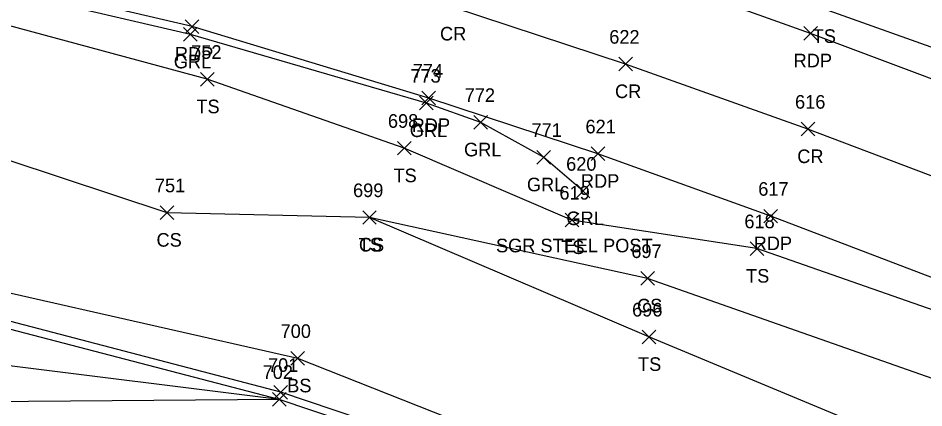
# Model space of a CAD drawing. Extents: x 1599569 to 1610055, y 642560 to 647860.
# Drawn here: x 1602648.3 to 1602781.6, y 647435 to 647492.4 of the extents above; entities that cross this region are included whole.
import ezdxf

# ---------------------------------------------------------------- set-up
doc = ezdxf.new("R2010")
doc.units = 0
for name, color, linetype in [('L_A', 7, 'Continuous'), ('L_I', 7, 'Continuous'), ('L_TIC', 7, 'Continuous'), ('LELB', 7, 'Continuous'), ('P_A', 7, 'Continuous'), ('P_I', 7, 'Continuous'), ('P_TIC', 7, 'Continuous'), ('PET', 7, 'Continuous'), ('PRC', 7, 'Continuous'), ('R_A', 7, 'Continuous'), ('R_C', 7, 'Continuous'), ('R_I', 7, 'Continuous'), ('R_TIC', 7, 'Continuous'), ('RGR', 7, 'Continuous')]:
    doc.layers.add(name, color=color, linetype=linetype)

msp = doc.modelspace()

# ---------------------------------------------------------------- linework, layer by layer
at = {"layer": 'L_TIC'}
for points in [[(1602675.17, 647482.37), (1602677.17, 647484.37)], [(1602677.17, 647482.37), (1602675.17, 647484.37)], [(1602704.16, 647472.23), (1602706.16, 647474.23)], [(1602706.16, 647472.23), (1602704.16, 647474.23)], [(1602669.27, 647462.75), (1602671.27, 647464.75)], [(1602671.27, 647462.75), (1602669.27, 647464.75)], [(1602699.04, 647462.04), (1602701.04, 647464.04)], [(1602701.04, 647462.04), (1602699.04, 647464.04)], [(1602699.04, 647462.04), (1602701.04, 647464.04)], [(1602701.04, 647462.04), (1602699.04, 647464.04)], [(1602728.83, 647461.67), (1602730.83, 647463.67)], [(1602730.83, 647461.67), (1602728.83, 647463.67)], [(1602756.03, 647457.46), (1602758.03, 647459.46)], [(1602758.03, 647457.46), (1602756.03, 647459.46)], [(1602739.96, 647453.08), (1602741.96, 647455.08)], [(1602741.96, 647453.08), (1602739.96, 647455.08)], [(1602740.14, 647444.48), (1602742.14, 647446.48)], [(1602742.14, 647444.48), (1602740.14, 647446.48)], [(1602688.48, 647441.33), (1602690.48, 647443.33)], [(1602690.48, 647441.33), (1602688.48, 647443.33)], [(1602685.76, 647435.3), (1602687.76, 647437.3)], [(1602687.76, 647435.3), (1602685.76, 647437.3)], [(1602685.76, 647435.3), (1602687.76, 647437.3)], [(1602687.76, 647435.3), (1602685.76, 647437.3)], [(1602685.76, 647435.3), (1602687.76, 647437.3)], [(1602687.76, 647435.3), (1602685.76, 647437.3)], [(1602685.99, 647436.34), (1602687.99, 647438.34)], [(1602687.99, 647436.34), (1602685.99, 647438.34)]]:
    msp.add_lwpolyline(points, dxfattribs=at)
at = {"layer": 'LELB'}
for points in [[(1602834.18, 647471.37), (1602800.58, 647481.71), (1602766.83, 647493.71), (1602735.94, 647503.84), (1602713.49, 647512.26), (1602692.59, 647522.64), (1602679.82, 647526.83)], [(1602920.15, 647395.93), (1602878.36, 647413), (1602839.66, 647426.29), (1602797.14, 647444.47), (1602757.03, 647458.46), (1602729.83, 647462.67), (1602705.16, 647473.23), (1602676.17, 647483.37), (1602645.06, 647491.74), (1602608.39, 647499.39), (1602581.9, 647503.71), (1602538.18, 647509.07), (1602515.71, 647510.39), (1602496.95, 647511.81), (1602468.81, 647510.52), (1602437.53, 647504.14), (1602407.66, 647504.45), (1602378.45, 647504.43), (1602350.14, 647499.82), (1602309.52, 647489.18), (1602272.83, 647479.89), (1602236.83, 647468.86)], [(1602844.82, 647413.51), (1602810.8, 647429.9), (1602787.42, 647437.73), (1602740.96, 647454.08), (1602700.04, 647463.04), (1602670.27, 647463.75), (1602639.01, 647474.07), (1602621.95, 647482.89), (1602620.57, 647490.49), (1602611.15, 647487.69), (1602600.84, 647483.48), (1602570.08, 647479.67), (1602551.04, 647482.68)], [(1603012.49, 647326.24), (1602990.45, 647341.3), (1602973.77, 647353.11), (1602953.95, 647363.4), (1602916.83, 647376.34), (1602879.52, 647385.68), (1602861.45, 647391.05), (1602857.96, 647395.91), (1602856.57, 647396.23), (1602848.89, 647379.86), (1602843.21, 647377.7), (1602818.67, 647385.57), (1602771.25, 647404.63), (1602731.78, 647425.59), (1602689.48, 647442.33), (1602646.26, 647452.13), (1602605.47, 647460.82), (1602615.77, 647472.63), (1602617.29, 647479.52), (1602614.47, 647480.43), (1602602, 647462.58), (1602569.34, 647464.61)], [(1602941.78, 647364.94), (1602916.7, 647374.33), (1602878.74, 647383.8), (1602864.18, 647385.07), (1602847.83, 647371.45), (1602840.84, 647371.94), (1602817.04, 647381.69), (1602769.81, 647402.39), (1602730.45, 647422.72), (1602686.99, 647437.34), (1602646.16, 647448.05), (1602607.13, 647455.67), (1602560.59, 647462.73), (1602528.15, 647452.11), (1602504.4, 647431.52), (1602495.06, 647409.31), (1602489.51, 647381.97), (1602486.55, 647364.53)], [(1602997.22, 647343.55), (1602982.64, 647359.24), (1602956.26, 647371.23), (1602923.49, 647383.78), (1602881.48, 647394.49), (1602864.86, 647399.2), (1602857.7, 647404.45), (1602852.15, 647401.21), (1602844.53, 647381.78), (1602821.22, 647392.08), (1602783.51, 647427.85), (1602741.14, 647445.48), (1602700.04, 647463.04)], [(1602941.34, 647363.29), (1602915.67, 647371.75), (1602877.66, 647379.52), (1602865.48, 647379.11), (1602848.78, 647367.3), (1602839.38, 647367.46), (1602815.63, 647378.56), (1602768.2, 647398.54), (1602730, 647421.7), (1602686.76, 647436.3), (1602645.94, 647446.93), (1602606.96, 647454.27), (1602560.51, 647460.83), (1602529.36, 647450.31), (1602505.68, 647431.34)], [(1602686.76, 647436.3), (1602644.67, 647441.5), (1602603.76, 647449.22), (1602559.9, 647457.97), (1602529.4, 647445.04)], [(1602686.76, 647436.3), (1602643.7, 647435.94), (1602601.62, 647443.37), (1602558.17, 647448.12), (1602529.4, 647445.04)]]:
    msp.add_lwpolyline(points, dxfattribs=at)
at = {"layer": 'P_TIC'}
for points in [[(1602672.93, 647490.11), (1602674.93, 647492.11)], [(1602674.93, 647490.11), (1602672.93, 647492.11)], [(1602763.94, 647489.12), (1602765.94, 647491.12)], [(1602765.94, 647489.12), (1602763.94, 647491.12)], [(1602736.72, 647484.6), (1602738.72, 647486.6)], [(1602738.72, 647484.6), (1602736.72, 647486.6)], [(1602707.76, 647479.61), (1602709.76, 647481.61)], [(1602709.76, 647479.61), (1602707.76, 647481.61)], [(1602763.54, 647475.04), (1602765.54, 647477.04)], [(1602765.54, 647475.04), (1602763.54, 647477.04)], [(1602732.65, 647471.41), (1602734.65, 647473.41)], [(1602734.65, 647471.41), (1602732.65, 647473.41)], [(1602758.07, 647462.24), (1602760.07, 647464.24)], [(1602760.07, 647462.24), (1602758.07, 647464.24)]]:
    msp.add_lwpolyline(points, dxfattribs=at)
at = {"layer": 'PET'}
for points in [[(1602905.04, 647435.16), (1602871.23, 647448.73), (1602854.79, 647455.39), (1602851.89, 647458.31), (1602832.84, 647465.97), (1602826.47, 647466.63), (1602798.9, 647477.36), (1602764.94, 647490.12), (1602734.4, 647501.05), (1602712.01, 647507.82), (1602692.31, 647514.03), (1602689.68, 647516.42), (1602659.67, 647523.94), (1602639.42, 647528.36)], [(1602921.43, 647398.55), (1602879.84, 647415.39), (1602841.76, 647430.73), (1602798.53, 647448.18), (1602759.07, 647463.24), (1602733.65, 647472.41), (1602708.76, 647480.61), (1602673.93, 647491.11), (1602636.13, 647499.95), (1602599.54, 647506.52), (1602572.66, 647510.09), (1602538.1, 647513.57), (1602515.34, 647514.89), (1602496.48, 647515.72), (1602467.73, 647515.18), (1602434.16, 647513.35), (1602407.64, 647511.45), (1602378.14, 647507.95), (1602349.73, 647503.67), (1602307.56, 647494.3), (1602272.4, 647484.22), (1602235.37, 647472.94)]]:
    msp.add_lwpolyline(points, dxfattribs=at)
at = {"layer": 'PRC'}
msp.add_lwpolyline([(1602927.12, 647412.15), (1602885.11, 647429.06), (1602847.57, 647444.53), (1602804.05, 647461.06), (1602764.54, 647476.04), (1602737.72, 647485.6), (1602711.98, 647494.07), (1602678.09, 647504.18), (1602638.82, 647513.36), (1602602.08, 647520.13), (1602573.57, 647523.94), (1602538.53, 647527.38), (1602522.02, 647528.41), (1602495.43, 647529.4), (1602476.58, 647529.51), (1602450.94, 647528.8), (1602428.92, 647527.79), (1602401.34, 647525.43), (1602374.1, 647521.93), (1602345.43, 647516.91), (1602315.11, 647510.44), (1602285.69, 647502.77), (1602253.57, 647492.91)], dxfattribs=at)
at = {"layer": 'R_TIC'}
for points in [[(1602672.7, 647488.97), (1602674.7, 647490.97)], [(1602674.7, 647488.97), (1602672.7, 647490.97)], [(1602707.42, 647478.87), (1602709.42, 647480.87)], [(1602709.42, 647478.87), (1602707.42, 647480.87)], [(1602715.41, 647476.03), (1602717.41, 647478.03)], [(1602717.41, 647476.03), (1602715.41, 647478.03)], [(1602724.66, 647470.89), (1602726.66, 647472.89)], [(1602726.66, 647470.89), (1602724.66, 647472.89)], [(1602730.47, 647465.92), (1602732.47, 647467.92)], [(1602732.47, 647465.92), (1602730.47, 647467.92)]]:
    msp.add_lwpolyline(points, dxfattribs=at)
at = {"layer": 'RGR'}
msp.add_lwpolyline([(1602731.47, 647466.92), (1602725.66, 647471.89), (1602716.41, 647477.03), (1602708.42, 647479.87), (1602673.7, 647489.97), (1602635.84, 647498.79), (1602599.09, 647505.45), (1602572.33, 647509.01), (1602537.88, 647512.26), (1602515.33, 647514.01), (1602496.86, 647514.8), (1602467.91, 647514.3), (1602452.58, 647512.83), (1602443.8, 647510.51), (1602436.69, 647507.27)], dxfattribs=at)

# ---------------------------------------------------------------- texts
at = {"layer": 'L_A'}
for s, p in [('TS', (1602765.24, 647488.71)), ('TS', (1602674.58, 647478.37)), ('TS', (1602703.57, 647468.23)), ('CS', (1602668.71, 647458.75)), ('TS', (1602698.45, 647458.04)), ('CS', (1602698.48, 647458.04)), ('TS', (1602728.24, 647457.67)), ('TS', (1602755.44, 647453.46)), ('CS', (1602739.4, 647449.08)), ('TS', (1602739.54, 647440.48)), ('BS', (1602687.93, 647437.33))]:
    msp.add_text(s, height=2, dxfattribs=at).set_placement(p)
at = {"layer": 'L_I'}
for s, p in [('752', (1602673.81, 647486.37)), ('698', (1602702.75, 647476.23)), ('751', (1602668.47, 647466.75)), ('699', (1602697.62, 647466.04)), ('699', (1602697.62, 647466.04)), ('619', (1602727.98, 647465.67)), ('618', (1602755.19, 647461.46)), ('697', (1602738.55, 647457.08)), ('696', (1602738.67, 647448.48)), ('700', (1602686.96, 647445.33)), ('702', (1602684.32, 647439.3)), ('702', (1602684.32, 647439.3)), ('702', (1602684.32, 647439.3)), ('701', (1602685.11, 647440.34))]:
    msp.add_text(s, height=2, dxfattribs=at).set_placement(p)
at = {"layer": 'P_A'}
for s, p in [('CR', (1602710.42, 647489.07)), ('RDP', (1602671.42, 647486.11)), ('RDP', (1602762.43, 647485.12)), ('CR', (1602736.16, 647480.6)), ('RDP', (1602706.25, 647475.61)), ('CR', (1602762.97, 647471.04)), ('RDP', (1602731.14, 647467.41)), ('RDP', (1602756.56, 647458.24))]:
    msp.add_text(s, height=2, dxfattribs=at).set_placement(p)
at = {"layer": 'P_I'}
for s, p in [('622', (1602735.31, 647488.6)), ('774', (1602706.4, 647483.61)), ('616', (1602762.64, 647479.04)), ('621', (1602731.81, 647475.41)), ('617', (1602757.23, 647466.24))]:
    msp.add_text(s, height=2, dxfattribs=at).set_placement(p)
at = {"layer": 'R_A'}
for p in [(1602671.25, 647484.97), (1602705.96, 647474.87), (1602713.95, 647472.03), (1602723.2, 647466.89), (1602729.01, 647461.92)]:
    msp.add_text('GRL', height=2, dxfattribs=at).set_placement(p)
at = {"layer": 'R_C'}
msp.add_text('SGR STEEL POST', height=2, dxfattribs=at).set_placement((1602718.65, 647457.92))
at = {"layer": 'R_I'}
for s, p in [('773', (1602706.05, 647482.87)), ('772', (1602714.04, 647480.03)), ('771', (1602723.87, 647474.89)), ('620', (1602728.97, 647469.92))]:
    msp.add_text(s, height=2, dxfattribs=at).set_placement(p)

doc.saveas('drawing.dxf')
